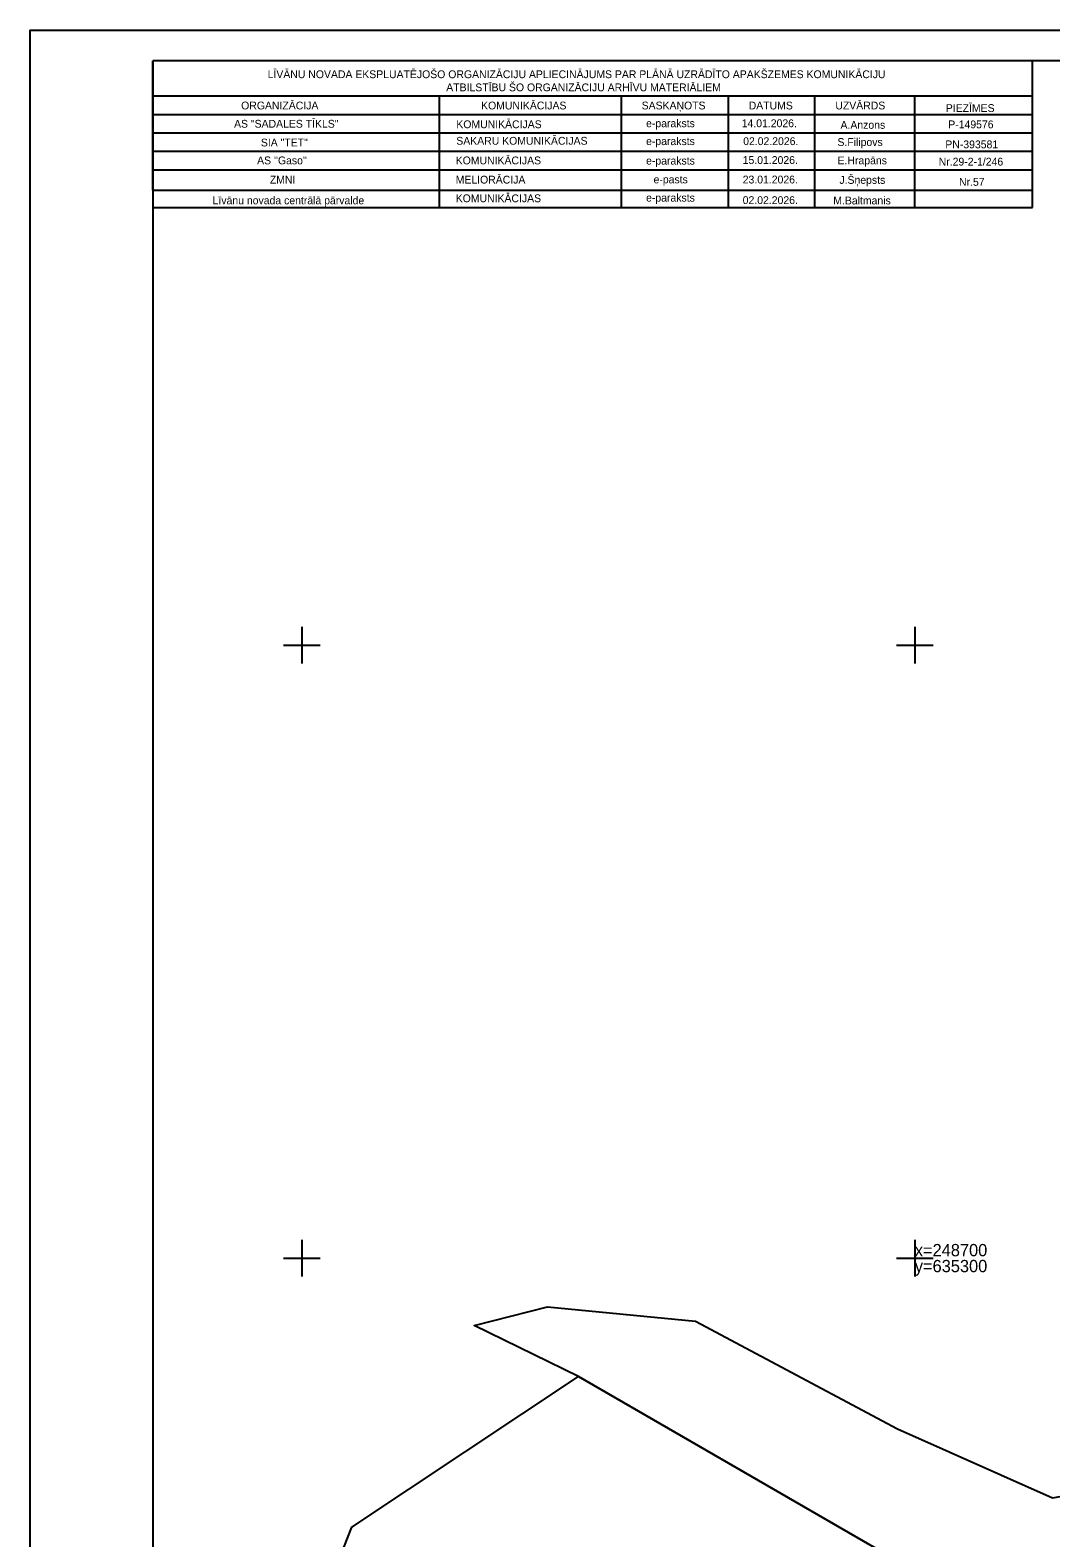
# Model space of a CAD drawing. Extents: x 635228 to 635525, y 248590 to 248800.
# Drawn here: x 635227.8 to 635311.1, y 248677.2 to 248800.2 of the extents above; entities that cross this region are included whole.
import ezdxf

# ---------------------------------------------------------------- set-up
doc = ezdxf.new("R2010")
doc.units = 0
for name, color, linetype in [('GEOD_ELEM_####_####_#', 7, 'Continuous'), ('GEOD_KORD_####_TKST_#', 7, 'Continuous'), ('RAMI_PLAN_####_TKST_#', 7, 'Continuous'), ('ROBZ_PROJ_####_####_#', 7, 'Continuous'), ('ROBZ_UZMR_####_####_#', 7, 'Continuous')]:
    doc.layers.add(name, color=color, linetype=linetype)

msp = doc.modelspace()

# ---------------------------------------------------------------- linework, layer by layer
at = {"layer": 'GEOD_ELEM_####_####_#'}
for p, q in [((635250, 248751.5), (635250, 248750)), ((635300, 248751.5), (635300, 248750)), ((635248.5, 248750), (635250, 248750)), ((635250, 248750), (635250, 248748.5)), ((635250, 248750), (635251.5, 248750)), ((635298.5, 248750), (635300, 248750)), ((635300, 248750), (635300, 248748.5)), ((635300, 248750), (635301.5, 248750)), ((635250, 248701.5), (635250, 248700)), ((635300, 248701.5), (635300, 248700)), ((635248.5, 248700), (635250, 248700)), ((635250, 248700), (635250, 248698.5)), ((635250, 248700), (635251.5, 248700)), ((635298.5, 248700), (635300, 248700)), ((635300, 248700), (635300, 248698.5)), ((635300, 248700), (635301.5, 248700))]:
    msp.add_line(p, q, dxfattribs=at)
at = {"layer": 'RAMI_PLAN_####_TKST_#'}
for p, q in [((635237.84, 248787.12), (635237.84, 248797.68)), ((635309.59, 248785.71), (635309.59, 248797.68)), ((635265.3, 248794.78), (635237.84, 248794.78)), ((635261.24, 248785.71), (635261.24, 248794.78)), ((635284.94, 248794.78), (635265.3, 248794.78)), ((635284.81, 248794.78), (635276.08, 248794.78)), ((635276.08, 248785.71), (635276.08, 248794.78)), ((635291.84, 248794.78), (635284.81, 248794.78)), ((635284.81, 248785.71), (635284.81, 248794.78)), ((635301.25, 248794.78), (635291.84, 248794.78)), ((635291.84, 248785.71), (635291.84, 248794.78)), ((635300, 248785.71), (635300.01, 248794.78)), ((635309.59, 248794.78), (635301.25, 248794.78)), ((635265.3, 248793.28), (635237.84, 248793.28)), ((635284.94, 248793.28), (635265.3, 248793.28)), ((635284.81, 248793.28), (635276.08, 248793.28)), ((635291.84, 248793.28), (635284.81, 248793.28)), ((635301.24, 248793.28), (635291.84, 248793.28)), ((635309.59, 248793.28), (635301.24, 248793.28)), ((635265.3, 248791.78), (635237.84, 248791.78)), ((635284.94, 248791.78), (635265.3, 248791.78)), ((635284.81, 248791.78), (635276.08, 248791.78)), ((635291.84, 248791.78), (635284.81, 248791.78)), ((635301.24, 248791.78), (635291.84, 248791.78)), ((635309.59, 248791.78), (635301.24, 248791.78)), ((635284.94, 248790.28), (635237.84, 248790.28)), ((635284.81, 248790.28), (635276.08, 248790.28)), ((635291.84, 248790.28), (635284.81, 248790.28)), ((635301.25, 248790.28), (635291.84, 248790.28)), ((635309.59, 248790.28), (635301.25, 248790.28))]:
    msp.add_line(p, q, dxfattribs=at)
for points in [[(635227.84, 248590.18), (635227.84, 248800.18), (635524.84, 248800.18), (635524.84, 248590.18)], [(635237.84, 248797.68), (635237.84, 248592.68), (635522.34, 248592.68), (635522.34, 248797.68)]]:
    msp.add_lwpolyline(points, close=True, dxfattribs=at)
for points in [[(635237.84, 248788.78), (635309.59, 248788.78)], [(635237.84, 248787.12), (635309.59, 248787.12)], [(635237.84, 248785.71), (635309.59, 248785.71)]]:
    msp.add_lwpolyline(points, dxfattribs=at)
at = {"layer": 'ROBZ_PROJ_####_####_#'}
msp.add_lwpolyline([(635363.32, 248797.68), (635360.89, 248769.92), (635360.48, 248762.62), (635343.34, 248703.12), (635337.46, 248688.66), (635327.79, 248676.83), (635329.65, 248676.37), (635325.54, 248659.74), (635315.4, 248665.6), (635272.58, 248690.35), (635264.06, 248694.51), (635270.04, 248696.02), (635282.1, 248694.85), (635298.6, 248686.07), (635311.24, 248680.45), (635322.5, 248682.38), (635341.09, 248726.31), (635346.48, 248751.58), (635353.47, 248778.8), (635354.81, 248797.68)], dxfattribs=at)
at = {"layer": 'ROBZ_UZMR_####_####_#'}
msp.add_lwpolyline([(635247.63, 248661.65), (635254.07, 248678.06), (635272.58, 248690.35), (635315.4, 248665.6), (635325.54, 248659.74), (635302.86, 248630.56)], close=True, dxfattribs=at)

# ---------------------------------------------------------------- texts
at = {"layer": 'GEOD_KORD_####_TKST_#'}
for s, p in [('x=248700', (635300, 248700.15)), ('y=635300', (635300, 248698.85))]:
    msp.add_text(s, height=1, dxfattribs=at).set_placement(p)
at = {"layer": 'RAMI_PLAN_####_TKST_#'}
for s, height, p in [('LĪVĀNU NOVADA EKSPLUATĒJOŠO ORGANIZĀCIJU APLIECINĀJUMS PAR PLĀNĀ UZRĀDĪTO APAKŠZEMES KOMUNIKĀCIJU ', 0.6375, (635247.21, 248796.26)), ('ATBILSTĪBU ŠO ORGANIZĀCIJU ARHĪVU MATERIĀLIEM', 0.6375, (635261.78, 248795.19)), ('ORGANIZĀCIJA', 0.6375, (635245.05, 248793.71)), ('KOMUNIKĀCIJAS', 0.6375, (635264.62, 248793.71)), ('SASKAŅOTS', 0.637, (635277.72, 248793.71)), ('DATUMS', 0.637, (635286.45, 248793.71)), ('UZVĀRDS', 0.637, (635293.52, 248793.71)), ('PIEZĪMES', 0.637, (635302.53, 248793.5)), ('AS "SADALES TĪKLS"', 0.6375, (635244.47, 248792.22)), ('KOMUNIKĀCIJAS', 0.6375, (635262.6, 248792.18)), ('SIA "TET"', 0.637, (635246.66, 248790.69)), ('SAKARU KOMUNIKĀCIJAS', 0.6375, (635262.6, 248790.83)), ('KOMUNIKĀCIJAS', 0.6375, (635262.55, 248789.23)), ('ZMNI', 0.637, (635247.39, 248787.66)), ('MELIORĀCIJA', 0.6375, (635262.55, 248787.66)), ('KOMUNIKĀCIJAS', 0.6375, (635262.55, 248786.14)), ('Līvānu novada centrālā pārvalde', 0.6375, (635242.72, 248785.97))]:
    msp.add_text(s, height=height, rotation=0.0007, dxfattribs=at).set_placement(p)
for s, height, p in [('e-paraksts', 0.637, (635278.08, 248792.26)), ('14.01.2026.', 0.6375, (635285.88, 248792.26)), ('A.Anzons', 0.637, (635293.94, 248792.13)), ('P-149576', 0.637, (635302.73, 248792.17)), ('e-paraksts', 0.637, (635278.08, 248790.8)), ('02.02.2026.', 0.6375, (635286, 248790.8)), ('S.Filipovs', 0.637, (635293.69, 248790.73)), ('PN-393581', 0.637, (635302.49, 248790.54)), ("AS ''Gaso''", 0.6375, (635246.35, 248789.23)), ('e-paraksts', 0.637, (635278.08, 248789.21)), ('15.01.2026.', 0.6375, (635285.96, 248789.26)), ('E.Hrapāns', 0.637, (635293.7, 248789.23)), ('Nr.29-2-1/246', 0.6375, (635301.95, 248789.13)), ('e-pasts', 0.637, (635278.69, 248787.68)), ('23.01.2026.', 0.6375, (635285.96, 248787.67)), ('J.Šņepsts', 0.637, (635293.85, 248787.64)), ('Nr.57', 0.637, (635303.61, 248787.48)), ('e-paraksts', 0.637, (635278.08, 248786.19)), ('02.02.2026.', 0.6375, (635285.96, 248785.99)), ('M.Baltmanis', 0.6375, (635293.35, 248785.96))]:
    msp.add_text(s, height=height, dxfattribs=at).set_placement(p)

doc.saveas('drawing.dxf')
